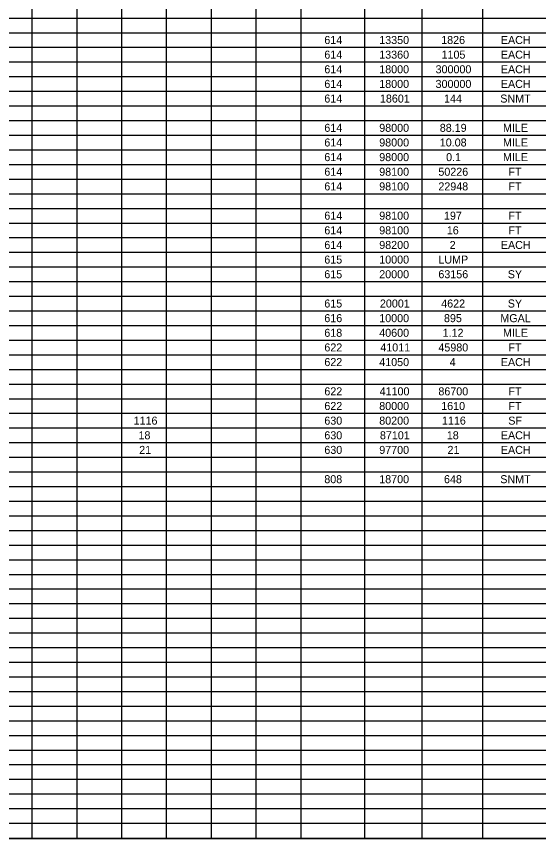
# Model space of a CAD drawing. Extents: x 91011267 to 91012802, y 37012737 to 37014266.
# Drawn here: x 91011765 to 91012252, y 37012737 to 37013505 of the extents above; entities that cross this region are included whole.
import ezdxf

# ---------------------------------------------------------------- set-up
doc = ezdxf.new("R2010")
doc.units = 0
doc.layers.add('SC_Scratch2', color=7, linetype='Continuous')
doc.layers.add('SH_Data', color=7, linetype='Continuous')

msp = doc.modelspace()

# ---------------------------------------------------------------- linework, layer by layer
at = {"layer": 'SC_Scratch2'}
msp.add_lwpolyline([(91011277.35, 37013787.1), (91012802.35, 37013787.1), (91012802.35, 37012737.1), (91011277.35, 37012737.1)], close=True, dxfattribs=at)
at = {"layer": 'SH_Data'}
for p, q in [((91011779.15, 37013598.97), (91011779.15, 37013503.28)), ((91011820.97, 37013598.97), (91011820.97, 37013503.28)), ((91011862.78, 37013598.97), (91011862.78, 37013503.28)), ((91011904.6, 37013598.97), (91011904.6, 37013503.28)), ((91011946.42, 37013598.97), (91011946.42, 37013503.28)), ((91011988.23, 37013598.97), (91011988.23, 37013503.28)), ((91012030.05, 37013598.97), (91012030.05, 37013503.28)), ((91012089.51, 37013598.97), (91012089.51, 37013503.28)), ((91012143.08, 37013598.97), (91012143.08, 37013503.28)), ((91012199.93, 37013598.97), (91012199.93, 37013503.28)), ((91011653.7, 37013503.28), (91011988.23, 37013503.28)), ((91011779.15, 37013503.28), (91011779.15, 37013489.61)), ((91011820.97, 37013503.28), (91011820.97, 37013489.61)), ((91011862.78, 37013503.28), (91011862.78, 37013489.61)), ((91011904.6, 37013503.28), (91011904.6, 37013489.61)), ((91011946.42, 37013503.28), (91011946.42, 37013489.61)), ((91011988.23, 37013503.28), (91012030.05, 37013503.28)), ((91011988.23, 37013503.28), (91011988.23, 37013489.61)), ((91012030.05, 37013503.28), (91012802.35, 37013503.28)), ((91012030.05, 37013503.28), (91012030.05, 37013489.61)), ((91012089.51, 37013503.28), (91012089.51, 37013489.61)), ((91012143.08, 37013503.28), (91012143.08, 37013489.61)), ((91012199.93, 37013503.28), (91012199.93, 37013489.61)), ((91011653.7, 37013489.61), (91011988.23, 37013489.61)), ((91011779.15, 37013489.61), (91011779.15, 37013462.27)), ((91011820.97, 37013489.61), (91011820.97, 37013462.27)), ((91011862.78, 37013489.61), (91011862.78, 37013462.27)), ((91011904.6, 37013489.61), (91011904.6, 37013462.27)), ((91011946.42, 37013489.61), (91011946.42, 37013462.27)), ((91011988.23, 37013489.61), (91012030.05, 37013489.61)), ((91011988.23, 37013489.61), (91011988.23, 37013462.27)), ((91012030.05, 37013489.61), (91012802.35, 37013489.61)), ((91012030.05, 37013489.61), (91012030.05, 37013462.27)), ((91012089.51, 37013489.61), (91012089.51, 37013462.27)), ((91012143.08, 37013489.61), (91012143.08, 37013462.27)), ((91012199.93, 37013489.61), (91012199.93, 37013462.27)), ((91011653.7, 37013475.94), (91011988.23, 37013475.94)), ((91011988.23, 37013475.94), (91012030.05, 37013475.94)), ((91012030.05, 37013475.94), (91012802.35, 37013475.94)), ((91011653.7, 37013462.27), (91011988.23, 37013462.27)), ((91011779.15, 37013462.27), (91011779.15, 37013448.6)), ((91011820.97, 37013462.27), (91011820.97, 37013448.6)), ((91011862.78, 37013462.27), (91011862.78, 37013448.6)), ((91011904.6, 37013462.27), (91011904.6, 37013448.6)), ((91011946.42, 37013462.27), (91011946.42, 37013448.6)), ((91011988.23, 37013462.27), (91012030.05, 37013462.27)), ((91011988.23, 37013462.27), (91011988.23, 37013448.6)), ((91012030.05, 37013462.27), (91012802.35, 37013462.27)), ((91012030.05, 37013462.27), (91012030.05, 37013448.6)), ((91012089.51, 37013462.27), (91012089.51, 37013448.6)), ((91012143.08, 37013462.27), (91012143.08, 37013448.6)), ((91012199.93, 37013462.27), (91012199.93, 37013448.6)), ((91011653.7, 37013448.6), (91011988.23, 37013448.6)), ((91011779.15, 37013448.6), (91011779.15, 37013434.93)), ((91011820.97, 37013448.6), (91011820.97, 37013434.93)), ((91011862.78, 37013448.6), (91011862.78, 37013434.93)), ((91011904.6, 37013448.6), (91011904.6, 37013434.93)), ((91011946.42, 37013448.6), (91011946.42, 37013434.93)), ((91011988.23, 37013448.6), (91012030.05, 37013448.6)), ((91011988.23, 37013448.6), (91011988.23, 37013434.93)), ((91012030.05, 37013448.6), (91012802.35, 37013448.6)), ((91012030.05, 37013448.6), (91012030.05, 37013434.93)), ((91012089.51, 37013448.6), (91012089.51, 37013434.93)), ((91012143.08, 37013448.6), (91012143.08, 37013434.93)), ((91012199.93, 37013448.6), (91012199.93, 37013434.93)), ((91011653.7, 37013434.93), (91011988.23, 37013434.93)), ((91011779.15, 37013434.93), (91011779.15, 37013421.26)), ((91011820.97, 37013434.93), (91011820.97, 37013421.26)), ((91011862.78, 37013434.93), (91011862.78, 37013421.26)), ((91011904.6, 37013434.93), (91011904.6, 37013421.26)), ((91011946.42, 37013434.93), (91011946.42, 37013421.26)), ((91011988.23, 37013434.93), (91012030.05, 37013434.93)), ((91011988.23, 37013434.93), (91011988.23, 37013421.26)), ((91012030.05, 37013434.93), (91012802.35, 37013434.93)), ((91012030.05, 37013434.93), (91012030.05, 37013421.26)), ((91012089.51, 37013434.93), (91012089.51, 37013421.26)), ((91012143.08, 37013434.93), (91012143.08, 37013421.26)), ((91012199.93, 37013434.93), (91012199.93, 37013421.26)), ((91011653.7, 37013421.26), (91011988.23, 37013421.26)), ((91011779.15, 37013421.26), (91011779.15, 37013216.2)), ((91011820.97, 37013421.26), (91011820.97, 37013216.2)), ((91011862.78, 37013421.26), (91011862.78, 37013216.2)), ((91011904.6, 37013421.26), (91011904.6, 37013216.2)), ((91011946.42, 37013421.26), (91011946.42, 37013216.2)), ((91011988.23, 37013421.26), (91012030.05, 37013421.26)), ((91011988.23, 37013421.26), (91011988.23, 37013216.2)), ((91012030.05, 37013421.26), (91012802.35, 37013421.26)), ((91012030.05, 37013421.26), (91012030.05, 37013216.2)), ((91012089.51, 37013421.26), (91012089.51, 37013216.2)), ((91012143.08, 37013421.26), (91012143.08, 37013216.2)), ((91012199.93, 37013421.26), (91012199.93, 37013216.2)), ((91011653.7, 37013407.59), (91011988.23, 37013407.59)), ((91011988.23, 37013407.59), (91012030.05, 37013407.59)), ((91012030.05, 37013407.59), (91012802.35, 37013407.59)), ((91011653.7, 37013393.91), (91011988.23, 37013393.91)), ((91011988.23, 37013393.91), (91012030.05, 37013393.91)), ((91012030.05, 37013393.91), (91012802.35, 37013393.91)), ((91011653.7, 37013380.24), (91011988.23, 37013380.24)), ((91011988.23, 37013380.24), (91012030.05, 37013380.24)), ((91012030.05, 37013380.24), (91012802.35, 37013380.24)), ((91011653.7, 37013366.57), (91011988.23, 37013366.57)), ((91011988.23, 37013366.57), (91012030.05, 37013366.57)), ((91012030.05, 37013366.57), (91012802.35, 37013366.57)), ((91011653.7, 37013352.9), (91011988.23, 37013352.9)), ((91011988.23, 37013352.9), (91012030.05, 37013352.9)), ((91012030.05, 37013352.9), (91012802.35, 37013352.9)), ((91011653.7, 37013339.23), (91011988.23, 37013339.23)), ((91011988.23, 37013339.23), (91012030.05, 37013339.23)), ((91012030.05, 37013339.23), (91012802.35, 37013339.23)), ((91011653.7, 37013325.56), (91011988.23, 37013325.56)), ((91011988.23, 37013325.56), (91012030.05, 37013325.56)), ((91012030.05, 37013325.56), (91012802.35, 37013325.56)), ((91011653.7, 37013311.89), (91011988.23, 37013311.89)), ((91011988.23, 37013311.89), (91012030.05, 37013311.89)), ((91012030.05, 37013311.89), (91012802.35, 37013311.89)), ((91011653.7, 37013298.22), (91011988.23, 37013298.22)), ((91011988.23, 37013298.22), (91012030.05, 37013298.22)), ((91012030.05, 37013298.22), (91012802.35, 37013298.22)), ((91011653.7, 37013284.55), (91011988.23, 37013284.55)), ((91011988.23, 37013284.55), (91012030.05, 37013284.55)), ((91012030.05, 37013284.55), (91012802.35, 37013284.55)), ((91011653.7, 37013270.88), (91011988.23, 37013270.88)), ((91011988.23, 37013270.88), (91012030.05, 37013270.88)), ((91012030.05, 37013270.88), (91012802.35, 37013270.88)), ((91011653.7, 37013257.21), (91011988.23, 37013257.21)), ((91011988.23, 37013257.21), (91012030.05, 37013257.21)), ((91012030.05, 37013257.21), (91012802.35, 37013257.21)), ((91011653.7, 37013243.54), (91011988.23, 37013243.54)), ((91011988.23, 37013243.54), (91012030.05, 37013243.54)), ((91012030.05, 37013243.54), (91012802.35, 37013243.54)), ((91011653.7, 37013229.87), (91011988.23, 37013229.87)), ((91011988.23, 37013229.87), (91012030.05, 37013229.87)), ((91012030.05, 37013229.87), (91012802.35, 37013229.87)), ((91011653.7, 37013216.2), (91011988.23, 37013216.2)), ((91011779.15, 37013216.2), (91011779.15, 37013202.53)), ((91011820.97, 37013216.2), (91011820.97, 37013202.53)), ((91011862.78, 37013216.2), (91011862.78, 37013202.53)), ((91011904.6, 37013216.2), (91011904.6, 37013202.53)), ((91011946.42, 37013216.2), (91011946.42, 37013202.53)), ((91011988.23, 37013216.2), (91012030.05, 37013216.2)), ((91011988.23, 37013216.2), (91011988.23, 37013202.53)), ((91012030.05, 37013216.2), (91012802.35, 37013216.2)), ((91012030.05, 37013216.2), (91012030.05, 37013202.53)), ((91012089.51, 37013216.2), (91012089.51, 37013202.53)), ((91012143.08, 37013216.2), (91012143.08, 37013202.53)), ((91012199.93, 37013216.2), (91012199.93, 37013202.53)), ((91011653.7, 37013202.53), (91011988.23, 37013202.53)), ((91011779.15, 37013202.53), (91011779.15, 37013188.86)), ((91011820.97, 37013202.53), (91011820.97, 37013188.86)), ((91011862.78, 37013202.53), (91011862.78, 37013188.86)), ((91011904.6, 37013202.53), (91011904.6, 37013188.86)), ((91011946.42, 37013202.53), (91011946.42, 37013188.86)), ((91011988.23, 37013202.53), (91012030.05, 37013202.53)), ((91011988.23, 37013202.53), (91011988.23, 37013188.86)), ((91012030.05, 37013202.53), (91012802.35, 37013202.53)), ((91012030.05, 37013202.53), (91012030.05, 37013188.86)), ((91012089.51, 37013202.53), (91012089.51, 37013188.86)), ((91012143.08, 37013202.53), (91012143.08, 37013188.86)), ((91012199.93, 37013202.53), (91012199.93, 37013188.86)), ((91011653.7, 37013188.86), (91011988.23, 37013188.86)), ((91011779.15, 37013188.86), (91011779.15, 37013147.85)), ((91011820.97, 37013188.86), (91011820.97, 37013147.85)), ((91011862.78, 37013188.86), (91011862.78, 37013147.85)), ((91011904.6, 37013188.86), (91011904.6, 37013147.85)), ((91011946.42, 37013188.86), (91011946.42, 37013147.85)), ((91011988.23, 37013188.86), (91012030.05, 37013188.86)), ((91011988.23, 37013188.86), (91011988.23, 37013147.85)), ((91012030.05, 37013188.86), (91012802.35, 37013188.86)), ((91012030.05, 37013188.86), (91012030.05, 37013147.85)), ((91012089.51, 37013188.86), (91012089.51, 37013147.85)), ((91012143.08, 37013188.86), (91012143.08, 37013147.85)), ((91012199.93, 37013188.86), (91012199.93, 37013147.85)), ((91011653.7, 37013175.19), (91011988.23, 37013175.19)), ((91011988.23, 37013175.19), (91012030.05, 37013175.19)), ((91012030.05, 37013175.19), (91012802.35, 37013175.19)), ((91011653.7, 37013161.52), (91011988.23, 37013161.52)), ((91011988.23, 37013161.52), (91012030.05, 37013161.52)), ((91012030.05, 37013161.52), (91012802.35, 37013161.52)), ((91011653.7, 37013147.85), (91011988.23, 37013147.85)), ((91011779.15, 37013147.85), (91011779.15, 37013134.18)), ((91011820.97, 37013147.85), (91011820.97, 37013134.18)), ((91011862.78, 37013147.85), (91011862.78, 37013134.18)), ((91011904.6, 37013147.85), (91011904.6, 37013134.18)), ((91011946.42, 37013147.85), (91011946.42, 37013134.18)), ((91011988.23, 37013147.85), (91012030.05, 37013147.85)), ((91011988.23, 37013147.85), (91011988.23, 37013134.18)), ((91012030.05, 37013147.85), (91012802.35, 37013147.85)), ((91012030.05, 37013147.85), (91012030.05, 37013134.18)), ((91012089.51, 37013147.85), (91012089.51, 37013134.18)), ((91012143.08, 37013147.85), (91012143.08, 37013134.18)), ((91012199.93, 37013147.85), (91012199.93, 37013134.18)), ((91011653.7, 37013134.18), (91011988.23, 37013134.18)), ((91011779.15, 37013134.18), (91011779.15, 37013120.51)), ((91011820.97, 37013134.18), (91011820.97, 37013120.51)), ((91011862.78, 37013134.18), (91011862.78, 37013120.51)), ((91011904.6, 37013134.18), (91011904.6, 37013120.51)), ((91011946.42, 37013134.18), (91011946.42, 37013120.51)), ((91011988.23, 37013134.18), (91012030.05, 37013134.18)), ((91011988.23, 37013134.18), (91011988.23, 37013120.51)), ((91012030.05, 37013134.18), (91012802.35, 37013134.18)), ((91012030.05, 37013134.18), (91012030.05, 37013120.51)), ((91012089.51, 37013134.18), (91012089.51, 37013120.51)), ((91012143.08, 37013134.18), (91012143.08, 37013120.51)), ((91012199.93, 37013134.18), (91012199.93, 37013120.51)), ((91011653.7, 37013120.51), (91011988.23, 37013120.51)), ((91011779.15, 37013120.51), (91011779.15, 37013079.5)), ((91011820.97, 37013120.51), (91011820.97, 37013079.5)), ((91011862.78, 37013120.51), (91011862.78, 37013079.5)), ((91011904.6, 37013120.51), (91011904.6, 37013079.5)), ((91011946.42, 37013120.51), (91011946.42, 37013079.5)), ((91011988.23, 37013120.51), (91012030.05, 37013120.51)), ((91011988.23, 37013120.51), (91011988.23, 37013079.5)), ((91012030.05, 37013120.51), (91012802.35, 37013120.51)), ((91012030.05, 37013120.51), (91012030.05, 37013079.5)), ((91012089.51, 37013120.51), (91012089.51, 37013079.5)), ((91012143.08, 37013120.51), (91012143.08, 37013079.5)), ((91012199.93, 37013120.51), (91012199.93, 37013079.5)), ((91011653.7, 37013106.84), (91011988.23, 37013106.84)), ((91011988.23, 37013106.84), (91012030.05, 37013106.84)), ((91012030.05, 37013106.84), (91012802.35, 37013106.84)), ((91011653.7, 37013093.17), (91011988.23, 37013093.17)), ((91011988.23, 37013093.17), (91012030.05, 37013093.17)), ((91012030.05, 37013093.17), (91012802.35, 37013093.17)), ((91011653.7, 37013079.5), (91011988.23, 37013079.5)), ((91011779.15, 37013079.5), (91011779.15, 37013065.83)), ((91011820.97, 37013079.5), (91011820.97, 37013065.83)), ((91011862.78, 37013079.5), (91011862.78, 37013065.83)), ((91011904.6, 37013079.5), (91011904.6, 37013065.83)), ((91011946.42, 37013079.5), (91011946.42, 37013065.83)), ((91011988.23, 37013079.5), (91012030.05, 37013079.5)), ((91011988.23, 37013079.5), (91011988.23, 37013065.83)), ((91012030.05, 37013079.5), (91012802.35, 37013079.5)), ((91012030.05, 37013079.5), (91012030.05, 37013065.83)), ((91012089.51, 37013079.5), (91012089.51, 37013065.83)), ((91012143.08, 37013079.5), (91012143.08, 37013065.83)), ((91012199.93, 37013079.5), (91012199.93, 37013065.83)), ((91011653.7, 37013065.83), (91011988.23, 37013065.83)), ((91011779.15, 37013065.83), (91011779.15, 37013052.16)), ((91011820.97, 37013065.83), (91011820.97, 37013052.16)), ((91011862.78, 37013065.83), (91011862.78, 37013052.16)), ((91011904.6, 37013065.83), (91011904.6, 37013052.16)), ((91011946.42, 37013065.83), (91011946.42, 37013052.16)), ((91011988.23, 37013065.83), (91012030.05, 37013065.83)), ((91011988.23, 37013065.83), (91011988.23, 37013052.16)), ((91012030.05, 37013065.83), (91012802.35, 37013065.83)), ((91012030.05, 37013065.83), (91012030.05, 37013052.16)), ((91012089.51, 37013065.83), (91012089.51, 37013052.16)), ((91012143.08, 37013065.83), (91012143.08, 37013052.16)), ((91012199.93, 37013065.83), (91012199.93, 37013052.16)), ((91011653.7, 37013052.16), (91011988.23, 37013052.16)), ((91011779.15, 37013052.16), (91011779.15, 37012737.1)), ((91011820.97, 37013052.16), (91011820.97, 37012737.1)), ((91011862.78, 37013052.16), (91011862.78, 37012737.1)), ((91011904.6, 37013052.16), (91011904.6, 37012737.1)), ((91011946.42, 37013052.16), (91011946.42, 37012737.1)), ((91011988.23, 37013052.16), (91012030.05, 37013052.16)), ((91011988.23, 37013052.16), (91011988.23, 37012737.1)), ((91012030.05, 37013052.16), (91012802.35, 37013052.16)), ((91012030.05, 37013052.16), (91012030.05, 37012737.1)), ((91012089.51, 37013052.16), (91012089.51, 37012737.1)), ((91012143.08, 37013052.16), (91012143.08, 37012737.1)), ((91012199.93, 37013052.16), (91012199.93, 37012737.1)), ((91011653.7, 37013038.49), (91011988.23, 37013038.49)), ((91011988.23, 37013038.49), (91012030.05, 37013038.49)), ((91012030.05, 37013038.49), (91012802.35, 37013038.49)), ((91011653.7, 37013024.82), (91011988.23, 37013024.82)), ((91011988.23, 37013024.82), (91012030.05, 37013024.82)), ((91012030.05, 37013024.82), (91012802.35, 37013024.82)), ((91011653.7, 37013011.15), (91011988.23, 37013011.15)), ((91011988.23, 37013011.15), (91012030.05, 37013011.15)), ((91012030.05, 37013011.15), (91012802.35, 37013011.15)), ((91011653.7, 37012997.48), (91011988.23, 37012997.48)), ((91011988.23, 37012997.48), (91012030.05, 37012997.48)), ((91012030.05, 37012997.48), (91012802.35, 37012997.48)), ((91011653.7, 37012983.81), (91011988.23, 37012983.81)), ((91011988.23, 37012983.81), (91012030.05, 37012983.81)), ((91012030.05, 37012983.81), (91012802.35, 37012983.81)), ((91011653.7, 37012970.14), (91011988.23, 37012970.14)), ((91011988.23, 37012970.14), (91012030.05, 37012970.14)), ((91012030.05, 37012970.14), (91012802.35, 37012970.14)), ((91011653.7, 37012956.47), (91011988.23, 37012956.47)), ((91011988.23, 37012956.47), (91012030.05, 37012956.47)), ((91012030.05, 37012956.47), (91012802.35, 37012956.47)), ((91011653.7, 37012942.8), (91011988.23, 37012942.8)), ((91011988.23, 37012942.8), (91012030.05, 37012942.8)), ((91012030.05, 37012942.8), (91012802.35, 37012942.8)), ((91011653.7, 37012929.13), (91011988.23, 37012929.13)), ((91011988.23, 37012929.13), (91012030.05, 37012929.13)), ((91012030.05, 37012929.13), (91012802.35, 37012929.13)), ((91011653.7, 37012915.46), (91011988.23, 37012915.46)), ((91011988.23, 37012915.46), (91012030.05, 37012915.46)), ((91012030.05, 37012915.46), (91012802.35, 37012915.46)), ((91011653.7, 37012901.79), (91011988.23, 37012901.79)), ((91011988.23, 37012901.79), (91012030.05, 37012901.79)), ((91012030.05, 37012901.79), (91012802.35, 37012901.79)), ((91011653.7, 37012888.12), (91011988.23, 37012888.12)), ((91011988.23, 37012888.12), (91012030.05, 37012888.12)), ((91012030.05, 37012888.12), (91012802.35, 37012888.12)), ((91011653.7, 37012874.45), (91011988.23, 37012874.45)), ((91011988.23, 37012874.45), (91012030.05, 37012874.45)), ((91012030.05, 37012874.45), (91012802.35, 37012874.45)), ((91011653.7, 37012860.78), (91011988.23, 37012860.78)), ((91011988.23, 37012860.78), (91012030.05, 37012860.78)), ((91012030.05, 37012860.78), (91012802.35, 37012860.78)), ((91011653.7, 37012847.11), (91011988.23, 37012847.11)), ((91011988.23, 37012847.11), (91012030.05, 37012847.11)), ((91012030.05, 37012847.11), (91012802.35, 37012847.11)), ((91011653.7, 37012833.44), (91011988.23, 37012833.44)), ((91011988.23, 37012833.44), (91012030.05, 37012833.44)), ((91012030.05, 37012833.44), (91012802.35, 37012833.44)), ((91011653.7, 37012819.77), (91011988.23, 37012819.77)), ((91011988.23, 37012819.77), (91012030.05, 37012819.77)), ((91012030.05, 37012819.77), (91012802.35, 37012819.77)), ((91011653.7, 37012806.1), (91011988.23, 37012806.1)), ((91011988.23, 37012806.1), (91012030.05, 37012806.1)), ((91012030.05, 37012806.1), (91012802.35, 37012806.1)), ((91011653.7, 37012792.43), (91011988.23, 37012792.43)), ((91011988.23, 37012792.43), (91012030.05, 37012792.43)), ((91012030.05, 37012792.43), (91012802.35, 37012792.43)), ((91011653.7, 37012778.76), (91011988.23, 37012778.76)), ((91011988.23, 37012778.76), (91012030.05, 37012778.76)), ((91012030.05, 37012778.76), (91012802.35, 37012778.76)), ((91011653.7, 37012765.09), (91011988.23, 37012765.09)), ((91011988.23, 37012765.09), (91012030.05, 37012765.09)), ((91012030.05, 37012765.09), (91012802.35, 37012765.09)), ((91011653.7, 37012751.42), (91011988.23, 37012751.42)), ((91011988.23, 37012751.42), (91012030.05, 37012751.42)), ((91012030.05, 37012751.42), (91012802.35, 37012751.42)), ((91011653.7, 37012737.1), (91011988.23, 37012737.1)), ((91011988.23, 37012737.1), (91012030.05, 37012737.1)), ((91012030.05, 37012737.1), (91012802.35, 37012737.1))]:
    msp.add_line(p, q, dxfattribs=at)

# ---------------------------------------------------------------- texts
for s, height, p in [('614', 7.486, (91012052.13, 37013479.03)), ('13350', 7.486, (91012103.39, 37013479.03)), ('1826', 7.486, (91012161.22, 37013479.03)), ('EACH', 7.486, (91012216.91, 37013479.03)), ('614', 7.486, (91012052.13, 37013465.36)), ('13360', 7.486, (91012103.39, 37013465.36)), ('1105', 7.486, (91012161.54, 37013465.36)), ('EACH', 7.486, (91012216.91, 37013465.36)), ('614', 7.486, (91012052.13, 37013451.69)), ('18000', 7.486, (91012103.39, 37013451.69)), ('300000', 7.486, (91012155.98, 37013451.69)), ('EACH', 7.486, (91012216.91, 37013451.69)), ('614', 7.486, (91012052.13, 37013438.02)), ('18000', 7.486, (91012103.39, 37013438.02)), ('300000', 7.486, (91012155.98, 37013438.02)), ('EACH', 7.486, (91012216.91, 37013438.02)), ('614', 7.486, (91012052.13, 37013424.35)), ('18601', 7.486, (91012104.03, 37013424.35)), ('144', 7.486, (91012163.86, 37013424.35)), ('SNMT', 7.486, (91012216.37, 37013424.35)), ('614', 7.486, (91012052.13, 37013397.01)), ('98000', 7.486, (91012103.39, 37013397.01)), ('88.19', 7.486, (91012159.9, 37013397.01)), ('MILE', 7.486, (91012218.89, 37013397.01)), ('614', 7.486, (91012052.13, 37013383.34)), ('98000', 7.486, (91012103.39, 37013383.34)), ('10.08', 7.486, (91012159.9, 37013383.34)), ('MILE', 7.486, (91012218.89, 37013383.34)), ('614', 7.486, (91012052.13, 37013369.67)), ('98000', 7.486, (91012103.39, 37013369.67)), ('0.1', 7.486, (91012165.81, 37013369.67)), ('MILE', 7.486, (91012218.89, 37013369.67)), ('614', 7.486, (91012052.13, 37013356)), ('98100', 7.486, (91012103.39, 37013356)), ('50226', 7.486, (91012158.59, 37013356)), ('FT', 7.486, (91012223.98, 37013356)), ('614', 7.486, (91012052.13, 37013342.33)), ('98100', 7.486, (91012103.39, 37013342.33)), ('22948', 7.486, (91012158.59, 37013342.33)), ('FT', 7.486, (91012223.98, 37013342.33)), ('614', 7.486, (91012052.13, 37013314.99)), ('98100', 7.486, (91012103.39, 37013314.99)), ('197', 7.486, (91012163.84, 37013314.99)), ('FT', 7.486, (91012223.98, 37013314.99)), ('614', 7.486, (91012052.13, 37013301.32)), ('98100', 7.486, (91012103.39, 37013301.32)), ('16', 7.486, (91012166.47, 37013301.32)), ('FT', 7.486, (91012223.98, 37013301.32)), ('614', 7.486, (91012052.13, 37013287.65)), ('98200', 7.486, (91012103.39, 37013287.65)), ('2', 7.49, (91012169.13, 37013287.65)), ('EACH', 7.486, (91012216.91, 37013287.65)), ('615', 7.486, (91012052.09, 37013273.98)), ('10000', 7.486, (91012103.39, 37013273.98)), ('LUMP', 7.486, (91012158.59, 37013273.98)), ('615', 7.486, (91012052.09, 37013260.31)), ('20000', 7.486, (91012103.39, 37013260.31)), ('63156', 7.486, (91012158.59, 37013260.31)), ('SY', 7.486, (91012223.39, 37013260.31)), ('615', 7.486, (91012052.09, 37013232.96)), ('20001', 7.486, (91012104.03, 37013232.96)), ('4622', 7.486, (91012161.25, 37013232.96)), ('SY', 7.486, (91012223.39, 37013232.96)), ('616', 7.486, (91012052.11, 37013219.29)), ('10000', 7.486, (91012103.39, 37013219.29)), ('895', 7.486, (91012163.82, 37013219.29)), ('MGAL', 7.486, (91012216.44, 37013219.29)), ('618', 7.486, (91012052.11, 37013205.62)), ('40600', 7.486, (91012103.39, 37013205.62)), ('1.12', 7.486, (91012162.57, 37013205.62)), ('MILE', 7.486, (91012218.89, 37013205.62)), ('622', 7.486, (91012052.15, 37013191.95)), ('41011', 7.486, (91012104.38, 37013191.95)), ('45980', 7.486, (91012158.6, 37013191.95)), ('FT', 7.486, (91012223.98, 37013191.95)), ('622', 7.486, (91012052.15, 37013178.28)), ('41050', 7.486, (91012103.39, 37013178.28)), ('4', 7.49, (91012169.11, 37013178.28)), ('EACH', 7.486, (91012216.91, 37013178.28)), ('622', 7.486, (91012052.15, 37013150.94)), ('41100', 7.486, (91012103.74, 37013150.94)), ('86700', 7.486, (91012158.6, 37013150.94)), ('FT', 7.486, (91012223.98, 37013150.94)), ('622', 7.486, (91012052.15, 37013137.27)), ('80000', 7.486, (91012103.39, 37013137.27)), ('1610', 7.486, (91012161.23, 37013137.27)), ('FT', 7.486, (91012223.98, 37013137.27)), ('1116', 7.486, (91011874.1, 37013123.6)), ('630', 7.486, (91012052.13, 37013123.6)), ('80200', 7.486, (91012103.39, 37013123.6)), ('1116', 7.486, (91012161.92, 37013123.6)), ('SF', 7.486, (91012223.84, 37013123.6)), ('18', 7.486, (91011878.65, 37013109.93)), ('630', 7.486, (91012052.13, 37013109.93)), ('87101', 7.486, (91012104.03, 37013109.93)), ('18', 7.486, (91012166.46, 37013109.93)), ('EACH', 7.486, (91012216.91, 37013109.93)), ('21', 7.486, (91011879.31, 37013096.26)), ('630', 7.486, (91012052.13, 37013096.26)), ('97700', 7.486, (91012103.39, 37013096.26)), ('21', 7.486, (91012167.12, 37013096.26)), ('EACH', 7.486, (91012216.91, 37013096.26)), ('808', 7.486, (91012052.11, 37013068.92)), ('18700', 7.486, (91012103.39, 37013068.92)), ('648', 7.486, (91012163.84, 37013068.92)), ('SNMT', 7.486, (91012216.37, 37013068.92))]:
    msp.add_text(s, height=height, dxfattribs=at).set_placement(p)

doc.saveas('drawing.dxf')
